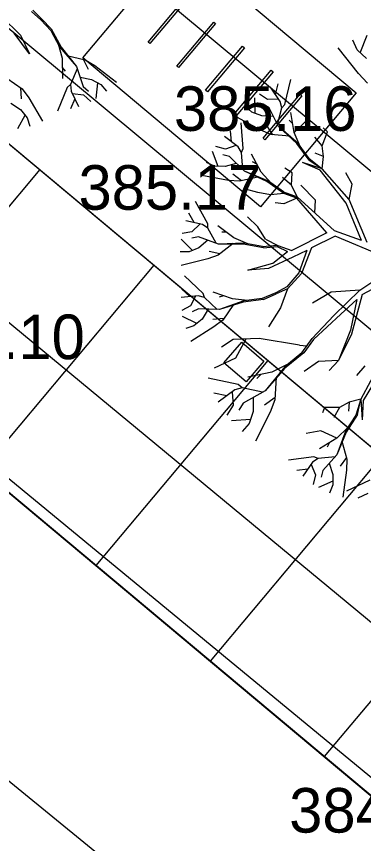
# Model space of a CAD drawing. Extents: x -438233 to -437334, y -1133133 to -1132623.
# Drawn here: x -438087.94 to -438082.12, y -1132988.01 to -1132974.1 of the extents above; entities that cross this region are included whole.
import ezdxf

# ---------------------------------------------------------------- set-up
doc = ezdxf.new("R2010")
doc.units = 0
for name, color, linetype in [('Default', 7, 'Continuous'), ('MOBILIÁŘ', 7, 'Continuous'), ('Vrstva 1', 7, 'Continuous'), ('Vrstva 10', 7, 'Continuous'), ('Vrstva 3', 7, 'Continuous'), ('Vrstva 50', 7, 'Continuous')]:
    doc.layers.add(name, color=color, linetype=linetype)

# ---------------------------------------------------------------- blocks, each defined once
blk = doc.blocks.new('A$C73EC33FB')
at = {"layer": 'Default'}
for points in [[(-39000, 25012), (0, 25012), (0, 0), (-39000, 0)], [(-32310, 18759), (-31900, 18759), (-31900, 9105), (-32310, 9105)], [(-26014, 18759), (-25605, 18759), (-25605, 9105), (-26014, 9105)], [(-19705, 18759), (-19295, 18759), (-19295, 9105), (-19705, 9105)], [(-13409, 18759), (-13000, 18759), (-13000, 9105), (-13409, 9105)], [(-7100, 18759), (-6690, 18759), (-6690, 9105), (-7100, 9105)]]:
    blk.add_lwpolyline(points, close=True, dxfattribs=at)

msp = doc.modelspace()

# ---------------------------------------------------------------- linework, layer by layer
at = {"layer": 'Vrstva 1'}
for p, q in [((-438091.577, -1132973.302), (-438066.281, -1132994.494)), ((-438087.693, -1132974.015), (-438087.537, -1132974.156)), ((-438087.668, -1132973.994), (-438087.52, -1132974.14)), ((-438088.194, -1132974.099), (-438087.875, -1132974.413)), ((-438087.366, -1132974.335), (-438087.537, -1132974.156)), ((-438087.52, -1132974.14), (-438087.36, -1132974.306)), ((-438087.366, -1132974.335), (-438087.22, -1132974.607)), ((-438087.36, -1132974.306), (-438087.196, -1132974.614)), ((-438087.726, -1132974.726), (-438087.982, -1132974.377)), ((-438087.875, -1132974.413), (-438087.726, -1132974.726)), ((-438082.221, -1132974.657), (-438082.294, -1132974.495)), ((-438082.169, -1132974.707), (-438082.053, -1132974.409)), ((-438087.247, -1132974.556), (-438087.18, -1132974.8)), ((-438087.22, -1132974.607), (-438086.937, -1132974.937)), ((-438087.196, -1132974.614), (-438086.937, -1132974.937)), ((-438082.201, -1132975.059), (-438082.539, -1132974.624)), ((-438087.097, -1132974.752), (-438086.79, -1132974.826)), ((-438082.068, -1132974.803), (-438082.221, -1132974.657)), ((-438087.18, -1132974.8), (-438087.17, -1132975.141)), ((-438086.822, -1132974.818), (-438086.743, -1132974.984)), ((-438086.79, -1132974.826), (-438086.631, -1132974.923)), ((-438086.631, -1132974.923), (-438086.267, -1132975.2)), ((-438087.175, -1132974.956), (-438087.127, -1132975.019)), ((-438086.923, -1132974.977), (-438087.037, -1132975.244)), ((-438086.937, -1132974.937), (-438086.823, -1132975.274)), ((-438082.046, -1132975.22), (-438082.201, -1132975.059)), ((-438088.107, -1132975.133), (-438087.851, -1132975.317)), ((-438086.877, -1132975.118), (-438086.683, -1132975.156)), ((-438086.683, -1132975.156), (-438086.529, -1132975.241)), ((-438083.439, -1132975.578), (-438083.335, -1132975.16)), ((-438087.877, -1132975.298), (-438087.866, -1132975.481)), ((-438087.851, -1132975.317), (-438087.739, -1132975.466)), ((-438087.093, -1132975.291), (-438087.256, -1132975.689)), ((-438087.037, -1132975.244), (-438087.093, -1132975.291)), ((-438087.037, -1132975.244), (-438087.027, -1132975.354)), ((-438086.823, -1132975.274), (-438086.737, -1132975.352)), ((-438086.581, -1132975.213), (-438086.61, -1132975.478)), ((-438086.529, -1132975.241), (-438086.435, -1132975.356)), ((-438083.514, -1132975.525), (-438083.676, -1132975.288)), ((-438083.592, -1132975.41), (-438083.548, -1132975.23)), ((-438087.739, -1132975.466), (-438087.505, -1132975.86)), ((-438086.965, -1132975.48), (-438087.035, -1132975.652)), ((-438087.027, -1132975.354), (-438086.902, -1132975.612)), ((-438087.005, -1132975.394), (-438086.819, -1132975.417)), ((-438086.819, -1132975.417), (-438086.697, -1132975.525)), ((-438083.933, -1132975.73), (-438083.943, -1132975.464)), ((-438083.727, -1132975.494), (-438083.865, -1132975.404)), ((-438088.039, -1132975.555), (-438087.875, -1132975.664)), ((-438083.99, -1132975.709), (-438084.099, -1132975.609)), ((-438083.702, -1132975.634), (-438083.8, -1132975.57)), ((-438083.541, -1132975.489), (-438083.727, -1132975.494)), ((-438083.488, -1132975.632), (-438083.514, -1132975.525)), ((-438083.488, -1132975.632), (-438083.439, -1132975.578)), ((-438083.069, -1132975.84), (-438083.023, -1132975.593)), ((-438087.801, -1132975.754), (-438087.927, -1132975.989)), ((-438087.875, -1132975.664), (-438087.764, -1132975.8)), ((-438083.824, -1132975.77), (-438083.99, -1132975.709)), ((-438083.541, -1132975.95), (-438083.702, -1132975.634)), ((-438083.56, -1132975.912), (-438083.488, -1132975.632)), ((-438083.281, -1132976.051), (-438083.339, -1132975.715)), ((-438087.764, -1132975.8), (-438087.72, -1132975.942)), ((-438083.842, -1132976.01), (-438084.243, -1132975.789)), ((-438084.135, -1132976.316), (-438084.168, -1132975.887)), ((-438083.628, -1132975.782), (-438083.824, -1132975.77)), ((-438083.308, -1132975.898), (-438083.364, -1132975.842)), ((-438083.281, -1132976.051), (-438083.069, -1132975.84)), ((-438084.335, -1132976.206), (-438084.35, -1132976.02)), ((-438083.67, -1132976.082), (-438083.842, -1132976.01)), ((-438083.638, -1132976.086), (-438083.739, -1132975.933)), ((-438083.238, -1132976.232), (-438083.541, -1132975.95)), ((-438083.213, -1132976.236), (-438083.541, -1132975.95)), ((-438082.812, -1132976.273), (-438082.723, -1132976.036)), ((-438082.8, -1132976.022), (-438082.8, -1132976.022)), ((-438082.723, -1132976.036), (-438082.794, -1132975.973)), ((-438084.223, -1132976.29), (-438084.452, -1132976.116)), ((-438083.356, -1132976.111), (-438083.67, -1132976.082)), ((-438083.178, -1132976.282), (-438083.281, -1132976.051)), ((-438082.812, -1132976.273), (-438082.933, -1132976.125)), ((-438084.435, -1132976.327), (-438084.594, -1132976.286)), ((-438084.26, -1132976.265), (-438084.435, -1132976.327)), ((-438084.164, -1132976.384), (-438084.223, -1132976.29)), ((-438083.031, -1132976.513), (-438083.238, -1132976.232)), ((-438083.029, -1132976.484), (-438083.213, -1132976.236)), ((-438082.785, -1132976.455), (-438082.812, -1132976.273)), ((-438084.557, -1132976.618), (-438084.651, -1132976.369)), ((-438084.368, -1132976.454), (-438084.481, -1132976.423)), ((-438084.164, -1132976.384), (-438084.135, -1132976.316)), ((-438084.145, -1132976.673), (-438084.164, -1132976.384)), ((-438083.836, -1132976.717), (-438083.998, -1132976.416)), ((-438082.785, -1132976.455), (-438082.927, -1132976.394)), ((-438084.617, -1132976.615), (-438084.752, -1132976.555)), ((-438084.252, -1132976.569), (-438084.441, -1132976.622)), ((-438084.114, -1132976.702), (-438084.368, -1132976.454)), ((-438083.91, -1132976.579), (-438083.982, -1132976.544)), ((-438082.844, -1132976.685), (-438083.14, -1132976.553)), ((-438082.808, -1132976.659), (-438083.14, -1132976.553)), ((-438083.031, -1132976.513), (-438082.808, -1132976.659)), ((-438083.029, -1132976.484), (-438083.029, -1132976.484)), ((-438083.029, -1132976.484), (-438082.808, -1132976.659)), ((-438082.808, -1132976.659), (-438082.785, -1132976.455)), ((-438087.552, -1132976.673), (-438090.442, -1132980.123)), ((-438084.441, -1132976.622), (-438084.617, -1132976.615)), ((-438083.739, -1132976.875), (-438084.114, -1132976.702)), ((-438083.714, -1132976.87), (-438084.114, -1132976.702)), ((-438083.666, -1132976.903), (-438083.836, -1132976.717)), ((-438083.315, -1132976.727), (-438083.435, -1132976.647)), ((-438083.323, -1132976.936), (-438083.315, -1132976.727)), ((-438082.409, -1132977.239), (-438082.844, -1132976.685)), ((-438082.358, -1132977.176), (-438082.808, -1132976.659)), ((-438082.304, -1132976.92), (-438082.411, -1132976.729)), ((-438094.467, -1132976.751), (-438069.171, -1132997.943)), ((-438084.382, -1132976.854), (-438084.832, -1132976.771)), ((-438084.196, -1132976.869), (-438084.382, -1132976.854)), ((-438084.164, -1132976.861), (-438084.31, -1132976.749)), ((-438083.889, -1132976.798), (-438084.196, -1132976.869)), ((-438083.46, -1132977.048), (-438083.714, -1132976.87)), ((-438083.323, -1132976.936), (-438083.478, -1132976.806)), ((-438083.89, -1132977.06), (-438084.097, -1132977.001)), ((-438083.453, -1132977.075), (-438083.739, -1132976.875)), ((-438083.228, -1132977.131), (-438083.323, -1132976.936)), ((-438082.921, -1132977.188), (-438083.17, -1132976.937)), ((-438082.358, -1132977.176), (-438082.304, -1132976.92)), ((-438083.676, -1132977.099), (-438083.89, -1132977.06)), ((-438083.453, -1132977.075), (-438083.676, -1132977.099)), ((-438083.46, -1132977.048), (-438083.228, -1132977.131)), ((-438083.228, -1132977.131), (-438083.453, -1132977.075)), ((-438083.235, -1132977.152), (-438083.453, -1132977.075)), ((-438082.602, -1132977.704), (-438083.228, -1132977.131)), ((-438084.731, -1132977.583), (-438084.94, -1132977.207)), ((-438083.453, -1132977.248), (-438083.602, -1132977.233)), ((-438083.235, -1132977.152), (-438083.453, -1132977.248)), ((-438082.729, -1132977.739), (-438083.235, -1132977.152)), ((-438082.931, -1132977.402), (-438082.921, -1132977.188)), ((-438082.152, -1132977.863), (-438082.409, -1132977.239)), ((-438082.053, -1132977.898), (-438082.358, -1132977.176)), ((-438084.958, -1132977.565), (-438085.049, -1132977.405)), ((-438084.403, -1132977.348), (-438084.403, -1132977.348)), ((-438084.822, -1132977.596), (-438085.101, -1132977.533)), ((-438083.888, -1132977.637), (-438084.064, -1132977.47)), ((-438084.867, -1132977.588), (-438084.999, -1132977.719)), ((-438084.73, -1132977.657), (-438084.822, -1132977.596)), ((-438084.73, -1132977.657), (-438084.731, -1132977.583)), ((-438084.592, -1132977.912), (-438084.73, -1132977.657)), ((-438084.293, -1132977.823), (-438084.564, -1132977.617)), ((-438083.76, -1132977.844), (-438083.888, -1132977.637)), ((-438082.152, -1132977.863), (-438082.602, -1132977.704)), ((-438084.999, -1132977.719), (-438085.161, -1132977.748)), ((-438084.885, -1132977.806), (-438085, -1132977.825)), ((-438084.552, -1132977.927), (-438084.885, -1132977.806)), ((-438084.418, -1132977.728), (-438084.497, -1132977.727)), ((-438084.06, -1132977.922), (-438084.293, -1132977.823)), ((-438083.76, -1132977.844), (-438083.555, -1132977.948)), ((-438082.731, -1132977.737), (-438083.321, -1132978.036)), ((-438082.594, -1132977.794), (-438082.987, -1132977.991)), ((-438081.428, -1132978.281), (-438082.594, -1132977.794)), ((-438084.989, -1132978.033), (-438085.178, -1132977.845)), ((-438084.731, -1132977.862), (-438084.881, -1132977.988)), ((-438084.307, -1132977.918), (-438084.556, -1132978.11)), ((-438084.118, -1132977.911), (-438084.552, -1132977.927)), ((-438084.138, -1132977.926), (-438084.552, -1132977.927)), ((-438083.795, -1132977.989), (-438084.138, -1132977.926)), ((-438083.813, -1132977.967), (-438084.118, -1132977.911)), ((-438083.564, -1132977.969), (-438083.392, -1132978.052)), ((-438083.555, -1132977.948), (-438083.321, -1132978.036)), ((-438085.043, -1132978.056), (-438085.193, -1132978.057)), ((-438084.881, -1132977.988), (-438085.043, -1132978.056)), ((-438084.556, -1132978.11), (-438084.731, -1132978.175)), ((-438084.531, -1132978.09), (-438084.709, -1132978.049)), ((-438083.639, -1132978.249), (-438083.392, -1132978.052)), ((-438083.069, -1132978.031), (-438083.303, -1132978.148)), ((-438083.069, -1132978.031), (-438083.201, -1132978.407)), ((-438082.987, -1132977.991), (-438083.156, -1132978.419)), ((-438084.731, -1132978.175), (-438085.176, -1132978.287)), ((-438084.056, -1132978.364), (-438083.639, -1132978.249)), ((-438083.303, -1132978.148), (-438083.71, -1132978.336)), ((-438085.636, -1132978.279), (-438088.526, -1132981.728)), ((-438083.71, -1132978.336), (-438084.056, -1132978.364)), ((-438084.809, -1132978.756), (-438085.123, -1132978.461)), ((-438083.201, -1132978.407), (-438083.402, -1132978.647)), ((-438083.156, -1132978.419), (-438083.392, -1132978.678)), ((-438082.178, -1132978.7), (-438081.841, -1132978.479)), ((-438083.402, -1132978.647), (-438083.589, -1132978.743)), ((-438083.392, -1132978.678), (-438083.581, -1132978.765)), ((-438083.392, -1132978.678), (-438083.51, -1132979)), ((-438082.139, -1132978.774), (-438081.761, -1132978.571)), ((-438084.891, -1132978.795), (-438085.177, -1132978.822)), ((-438085.031, -1132978.808), (-438085.166, -1132978.682)), ((-438084.936, -1132978.802), (-438085.022, -1132978.967)), ((-438084.785, -1132978.826), (-438084.891, -1132978.795)), ((-438084.785, -1132978.826), (-438084.809, -1132978.756)), ((-438084.318, -1132978.849), (-438084.64, -1132978.737)), ((-438084.466, -1132978.798), (-438084.542, -1132978.821)), ((-438083.589, -1132978.743), (-438083.817, -1132978.839)), ((-438083.793, -1132978.856), (-438083.581, -1132978.765)), ((-438082.656, -1132978.737), (-438082.973, -1132978.922)), ((-438082.178, -1132978.7), (-438082.656, -1132978.737)), ((-438082.615, -1132979.126), (-438082.178, -1132978.7)), ((-438082.139, -1132978.774), (-438082.318, -1132979.439)), ((-438084.576, -1132979.026), (-438084.785, -1132978.826)), ((-438084.123, -1132978.88), (-438084.533, -1132979.027)), ((-438084.139, -1132978.9), (-438084.533, -1132979.027)), ((-438084.302, -1132978.944), (-438084.481, -1132979.205)), ((-438084.066, -1132978.872), (-438084.318, -1132978.849)), ((-438083.793, -1132978.856), (-438084.139, -1132978.9)), ((-438083.817, -1132978.839), (-438084.123, -1132978.88)), ((-438082.496, -1132979.107), (-438082.227, -1132978.856)), ((-438082.227, -1132978.856), (-438082.332, -1132979.373)), ((-438085.022, -1132978.967), (-438085.168, -1132979.043)), ((-438084.888, -1132979.014), (-438084.992, -1132979.068)), ((-438084.533, -1132979.027), (-438084.888, -1132979.014)), ((-438084.723, -1132979.021), (-438084.828, -1132979.187)), ((-438083.51, -1132979), (-438083.714, -1132979.318)), ((-438084.916, -1132979.263), (-438085.154, -1132979.142)), ((-438084.828, -1132979.187), (-438084.963, -1132979.301)), ((-438084.462, -1132979.178), (-438084.644, -1132979.193)), ((-438084.481, -1132979.205), (-438084.628, -1132979.318)), ((-438082.976, -1132979.516), (-438082.615, -1132979.126)), ((-438082.953, -1132979.533), (-438082.496, -1132979.107)), ((-438084.963, -1132979.301), (-438085.102, -1132979.348)), ((-438084.628, -1132979.318), (-438085.016, -1132979.562)), ((-438082.332, -1132979.373), (-438082.536, -1132979.884)), ((-438082.318, -1132979.439), (-438082.536, -1132979.884)), ((-438084.303, -1132979.533), (-438084.502, -1132979.662)), ((-438083.867, -1132979.514), (-438084.303, -1132979.533)), ((-438084.091, -1132979.524), (-438084.264, -1132979.847)), ((-438083.192, -1132979.626), (-438083.867, -1132979.514)), ((-438083.192, -1132979.626), (-438083.065, -1132979.64)), ((-438083.15, -1132979.756), (-438082.976, -1132979.516)), ((-438082.953, -1132979.533), (-438083.116, -1132979.757)), ((-438083.116, -1132979.757), (-438083.443, -1132980.019)), ((-438083.15, -1132979.756), (-438083.439, -1132979.989)), ((-438087.364, -1132979.861), (-438087.364, -1132979.861)), ((-438083.72, -1132979.884), (-438086.61, -1132983.334)), ((-438084.264, -1132979.847), (-438084.622, -1132980.014)), ((-438082.873, -1132979.903), (-438083.112, -1132980.069)), ((-438082.536, -1132979.884), (-438082.873, -1132979.903)), ((-438082.536, -1132979.884), (-438082.695, -1132980.05)), ((-438083.439, -1132979.989), (-438083.766, -1132980.394)), ((-438083.443, -1132980.019), (-438083.766, -1132980.394)), ((-438083.385, -1132979.945), (-438083.658, -1132980.078)), ((-438082.094, -1132979.971), (-438082.235, -1132980.138)), ((-438081.835, -1132979.931), (-438082.159, -1132980.534)), ((-438081.759, -1132979.956), (-438082.123, -1132980.558)), ((-438084.219, -1132980.288), (-438084.724, -1132980.181)), ((-438083.658, -1132980.078), (-438084.058, -1132980.164)), ((-438083.841, -1132980.117), (-438083.906, -1132980.187)), ((-438083.583, -1132980.165), (-438083.604, -1132980.543)), ((-438084.151, -1132980.344), (-438084.279, -1132980.38)), ((-438084.151, -1132980.344), (-438084.219, -1132980.288)), ((-438083.811, -1132980.418), (-438084.151, -1132980.344)), ((-438084.414, -1132980.479), (-438084.631, -1132980.435)), ((-438084.279, -1132980.38), (-438084.556, -1132980.584)), ((-438084.321, -1132980.414), (-438084.307, -1132980.637)), ((-438083.766, -1132980.394), (-438084.139, -1132980.602)), ((-438084.139, -1132980.602), (-438084.212, -1132980.722)), ((-438083.967, -1132980.505), (-438083.97, -1132980.742)), ((-438083.601, -1132980.505), (-438083.779, -1132980.633)), ((-438083.604, -1132980.543), (-438083.683, -1132980.752)), ((-438082.359, -1132980.585), (-438082.519, -1132980.675)), ((-438082.359, -1132980.585), (-438082.365, -1132980.739)), ((-438082.159, -1132980.534), (-438082.359, -1132980.585)), ((-438082.159, -1132980.534), (-438082.245, -1132980.803)), ((-438082.218, -1132980.795), (-438082.159, -1132980.534)), ((-438082.159, -1132980.534), (-438082.14, -1132980.883)), ((-438082.123, -1132980.558), (-438082.14, -1132980.883)), ((-438084.307, -1132980.637), (-438084.409, -1132980.806)), ((-438083.97, -1132980.742), (-438084.036, -1132980.943)), ((-438083.683, -1132980.752), (-438083.931, -1132981.243)), ((-438082.772, -1132980.676), (-438082.805, -1132980.765)), ((-438082.519, -1132980.675), (-438082.772, -1132980.676)), ((-438082.519, -1132980.675), (-438082.614, -1132980.842)), ((-438084.014, -1132980.875), (-438084.332, -1132980.898)), ((-438082.245, -1132980.803), (-438082.412, -1132981.063)), ((-438082.218, -1132980.795), (-438082.406, -1132981.088)), ((-438084.036, -1132980.943), (-438084.152, -1132981.079)), ((-438082.381, -1132981.013), (-438082.561, -1132981.192)), ((-438082.833, -1132981.069), (-438083.08, -1132981.113)), ((-438082.561, -1132981.192), (-438082.833, -1132981.069)), ((-438082.412, -1132981.063), (-438082.561, -1132981.472)), ((-438082.406, -1132981.088), (-438082.561, -1132981.472)), ((-438082.561, -1132981.192), (-438082.853, -1132981.367)), ((-438082.694, -1132981.272), (-438082.727, -1132981.344)), ((-438082.477, -1132981.242), (-438082.394, -1132981.544)), ((-438081.803, -1132981.49), (-438084.693, -1132984.939)), ((-438082.948, -1132981.507), (-438083.374, -1132981.559)), ((-438082.97, -1132981.596), (-438083.134, -1132981.832)), ((-438082.878, -1132981.534), (-438082.97, -1132981.596)), ((-438082.878, -1132981.534), (-438082.948, -1132981.507)), ((-438082.59, -1132981.502), (-438082.878, -1132981.534)), ((-438082.561, -1132981.472), (-438082.801, -1132981.734)), ((-438082.402, -1132981.514), (-438082.508, -1132981.663)), ((-438082.394, -1132981.544), (-438082.4, -1132981.731)), ((-438083.05, -1132981.71), (-438083.234, -1132981.733)), ((-438082.994, -1132981.634), (-438082.923, -1132981.807)), ((-438082.801, -1132981.734), (-438082.826, -1132981.848)), ((-438082.69, -1132981.612), (-438082.63, -1132981.8)), ((-438082.4, -1132981.731), (-438082.465, -1132982.185)), ((-438082.923, -1132981.807), (-438082.959, -1132981.967)), ((-438082.63, -1132981.8), (-438082.628, -1132981.976)), ((-438082.628, -1132981.916), (-438082.874, -1132982.021)), ((-438082.628, -1132981.976), (-438082.684, -1132982.113)), ((-438082.009, -1132981.897), (-438082.399, -1132982.081)), ((-438082.042, -1132982.122), (-438082.21, -1132982.202)), ((-438079.887, -1132983.095), (-438082.777, -1132986.545))]:
    msp.add_line(p, q, dxfattribs=at)
for points in [[(-438083.813, -1132977.967), (-438083.567, -1132977.945)], [(-438083.795, -1132977.989), (-438083.564, -1132977.969)]]:
    msp.add_lwpolyline(points, dxfattribs=at)
msp.add_arc((-438057.962, -1132951.913), 27.6, 199.5386, 254.3601, dxfattribs=at)
at = {"layer": 'Vrstva 10'}
for points in [[(-438091.201, -1132969.023), (-438075.155, -1132982.388)], [(-438092.752, -1132970.399), (-438076.4, -1132984.021)], [(-438095.722, -1132972.904), (-438079.649, -1132986.224)], [(-438097.077, -1132974.44), (-438080.864, -1132987.825)], [(-438100.332, -1132976.931), (-438084.087, -1132990.217)]]:
    msp.add_lwpolyline(points, dxfattribs=at)
at = {"layer": 'Vrstva 50'}
for points in [[(-438091.577, -1132973.302), (-438066.273, -1132994.5), (-438069.163, -1132997.95), (-438094.467, -1132976.751)], [(-438084.161, -1132979.574), (-438083.788, -1132979.893), (-438084.087, -1132980.243), (-438084.46, -1132979.924)]]:
    msp.add_lwpolyline(points, close=True, dxfattribs=at)

# ---------------------------------------------------------------- block references
at = {"layer": 'MOBILIÁŘ', "xscale": 0.0001, "yscale": 9.999999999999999e-05, "rotation": -39.966187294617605}
msp.add_blockref('A$C73EC33FB', (-438083.843, -1132977.3), dxfattribs=at)

# ---------------------------------------------------------------- texts
at = {"layer": 'Vrstva 3'}
for s, p in [('385.16 ', (-438085.3, -1132976.022)), ('385.17 ', (-438086.903, -1132977.348)), ('385.10 ', (-438089.864, -1132979.861)), ('384.86 ', (-438083.364, -1132987.825))]:
    msp.add_text(s, height=0.75, dxfattribs=at).set_placement(p)

doc.saveas('drawing.dxf')
